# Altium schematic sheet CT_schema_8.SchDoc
size 274 x 160 mm
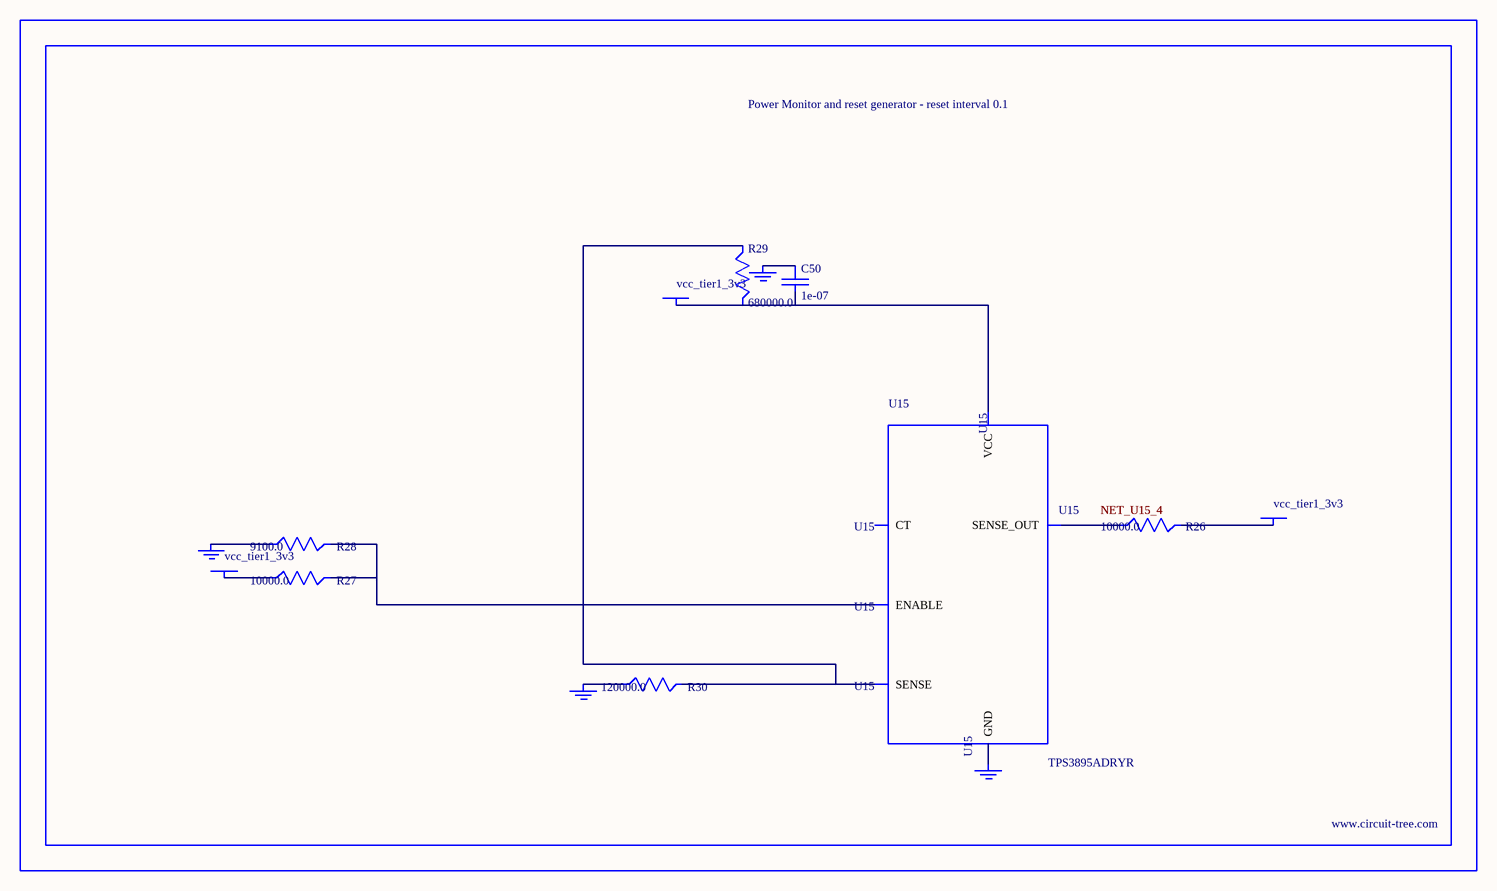
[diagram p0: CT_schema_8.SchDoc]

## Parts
BORDER7  (no value)
C50  1e-07  [C0402]
GND_INSTANCE_7_0  (no value)
GND_INSTANCE_7_1  (no value)
GND_INSTANCE_7_2  (no value)
GND_INSTANCE_7_3  (no value)
POWER_INSTANCE_7_0  vcc_tier1_3v3
POWER_INSTANCE_7_1  vcc_tier1_3v3
POWER_INSTANCE_7_2  vcc_tier1_3v3
R26  10000.0  [R0603]
R27  10000.0  [R0603]
R28  9100.0  [R0603]
R29  680000.0  [R0603]
R30  120000.0  [R0603]
U15  TPS3895ADRYR  [SON-6]

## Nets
NetC50_1: C50.1 GND_INSTANCE_7_2.0(GND)
NetC50_2: C50.2 POWER_INSTANCE_7_2.0(PWR) R29.2 U15.6(VCC)
NetGND_INSTANCE_7_0_0: GND_INSTANCE_7_0.0(GND) R28.1
NetGND_INSTANCE_7_1_0: GND_INSTANCE_7_1.0(GND) R30.1
NetGND_INSTANCE_7_3_0: GND_INSTANCE_7_3.0(GND) U15.2(GND)
NetPOWER_INSTANCE_7_0_0: POWER_INSTANCE_7_0.0(PWR) R27.1
NetPOWER_INSTANCE_7_1_0: POWER_INSTANCE_7_1.0(PWR) R26.2
NetR26_1: R26.1 U15.4(SENSE_OUT)
NetR27_2: R27.2 R28.2 U15.1(ENABLE)
NetR29_1: R29.1 R30.2 U15.3(SENSE)

Not connected (* = marked no-connect by the designer): U15 5(CT)

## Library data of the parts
BORDER7 = BORDER_PAGE7
C50 = C0402C104K3RACTU
GND_INSTANCE_7_0-GND_INSTANCE_7_3 = GND
POWER_INSTANCE_7_0-POWER_INSTANCE_7_2 = PWR
R26 R27 = RC0603JR-0710KL
R28 = RC0603JR-079K1L
R29 = RC0603JR-07680KL
R30 = RC0603JR-07120KL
